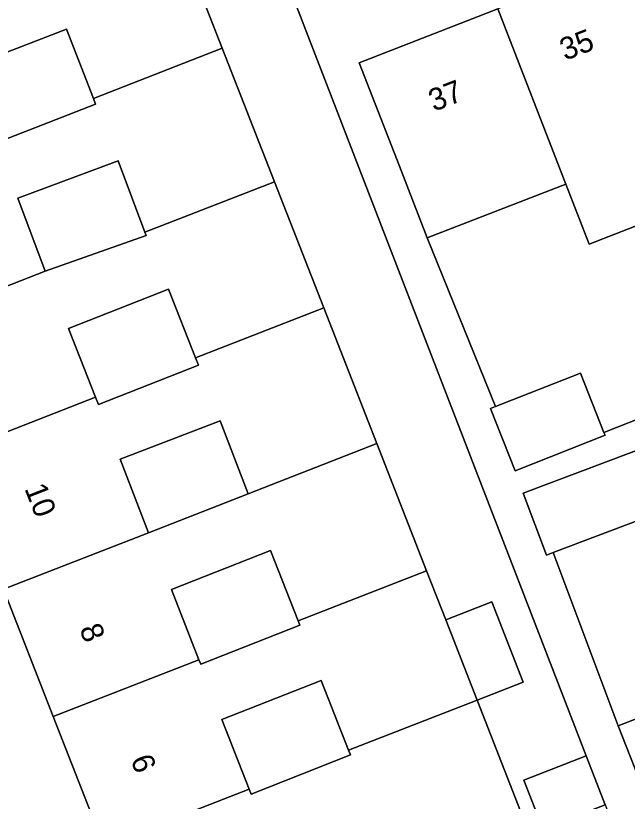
# Model space of a CAD drawing. Extents: x 159680 to 160786, y 387323 to 388340.
# Drawn here: x 160037.27 to 160064.76, y 387705.01 to 387740.35 of the extents above; entities that cross this region are included whole.
import ezdxf

# ---------------------------------------------------------------- set-up
doc = ezdxf.new("R2010")
doc.units = 0
for name, color, linetype in [('IMGEO_Erf', 7, 'Continuous'), ('IMGEO_Pand', 7, 'Continuous'), ('IMGEO_Pand_nummerreeks', 7, 'Continuous')]:
    doc.layers.add(name, color=color, linetype=linetype)

msp = doc.modelspace()

# ---------------------------------------------------------------- linework, layer by layer
at = {"layer": 'IMGEO_Erf'}
for points in [[(160063.763, 387704.855), (160060.968, 387703.763), (160060.112, 387705.953), (160062.906, 387707.046), (160049.712, 387741.251), (160047.668, 387746.549), (160047.477, 387746.967)], [(160044.3, 387744.642), (160046.55, 387738.886), (160048.898, 387732.879), (160051.117, 387727.204), (160053.501, 387721.103), (160055.739, 387715.38), (160056.604, 387713.166), (160058.678, 387713.977), (160060.087, 387710.373), (160058.013, 387709.563), (160060.342, 387703.605), (160062.693, 387697.59), (160056.921, 387695.334), (160055.624, 387698.652), (160051.143, 387696.9), (160052.452, 387693.552), (160045.92, 387690.998), (160043.556, 387697.046), (160041.227, 387703.003), (160038.953, 387708.82), (160036.716, 387714.544)], [(160049.712, 387741.251), (160062.906, 387707.046), (160063.763, 387704.855), (160067.164, 387696.141)], [(160068.113, 387723.336), (160063.713, 387721.604), (160063.764, 387721.474), (160059.714, 387719.879), (160058.612, 387722.678), (160058.842, 387722.769), (160055.766, 387730.35), (160054.513, 387733.571), (160052.7, 387738.23), (160058.934, 387740.655)], [(160068.893, 387732.348), (160063.049, 387730.075), (160061.999, 387732.775), (160055.766, 387730.35), (160058.842, 387722.769), (160062.662, 387724.273), (160063.713, 387721.604), (160068.113, 387723.336)], [(160065.622, 387705.162), (160064.358, 387708.4), (160061.428, 387716.201), (160061.123, 387716.086), (160060.074, 387718.864), (160066.203, 387721.178)], [(160067.252, 387718.4), (160061.428, 387716.201), (160064.358, 387708.4), (160070.388, 387710.753)]]:
    msp.add_lwpolyline(points, dxfattribs=at)
for points in [[(160040.757, 387736.624), (160039.547, 387739.743), (160035.038, 387737.994), (160036.254, 387734.86), (160036.348, 387734.617), (160040.857, 387736.366)], [(160038.589, 387728.848), (160043.128, 387730.452), (160043.071, 387730.603), (160041.869, 387733.821), (160037.36, 387732.135)], [(160040.985, 387722.858), (160045.482, 387724.623), (160045.352, 387724.953), (160044.139, 387728.043), (160039.642, 387726.278), (160040.854, 387723.191)], [(160046.457, 387722.115), (160041.962, 387720.394), (160043.229, 387717.087), (160047.71, 387718.842)], [(160045.581, 387711.183), (160050.035, 387712.929), (160049.959, 387713.123), (160048.719, 387716.285), (160044.265, 387714.539), (160045.504, 387711.378)], [(160052.233, 387707.306), (160050.995, 387710.446), (160046.533, 387708.686), (160047.768, 387705.557), (160047.855, 387705.336), (160052.316, 387707.096)]]:
    msp.add_lwpolyline(points, close=True, dxfattribs=at)
at = {"layer": 'IMGEO_Pand'}
for points in [[(160046.55, 387738.886), (160044.3, 387744.642), (160027.515, 387738.08), (160029.764, 387732.326), (160036.254, 387734.86), (160035.038, 387737.994), (160039.547, 387739.743), (160040.757, 387736.624)], [(160064.777, 387742.928), (160058.934, 387740.655), (160061.999, 387732.775), (160063.049, 387730.075), (160068.893, 387732.348), (160067.843, 387735.048)], [(160058.934, 387740.655), (160052.7, 387738.23), (160054.513, 387733.571), (160055.766, 387730.35), (160061.999, 387732.775)], [(160040.757, 387736.624), (160040.857, 387736.366), (160036.348, 387734.617), (160036.254, 387734.86), (160029.764, 387732.326), (160032.112, 387726.319), (160038.589, 387728.848), (160037.36, 387732.135), (160041.869, 387733.821), (160043.071, 387730.603), (160048.898, 387732.879), (160046.55, 387738.886)], [(160032.112, 387726.319), (160034.331, 387720.644), (160040.854, 387723.191), (160039.642, 387726.278), (160044.139, 387728.043), (160045.352, 387724.953), (160051.117, 387727.204), (160048.898, 387732.879), (160043.071, 387730.603), (160043.128, 387730.452), (160038.589, 387728.848)], [(160043.229, 387717.087), (160041.962, 387720.394), (160046.457, 387722.115), (160047.71, 387718.842), (160053.501, 387721.103), (160051.117, 387727.204), (160045.352, 387724.953), (160045.482, 387724.623), (160040.985, 387722.858), (160040.854, 387723.191), (160034.331, 387720.644), (160036.716, 387714.544)], [(160062.662, 387724.273), (160058.842, 387722.769), (160058.612, 387722.678), (160059.714, 387719.879), (160063.764, 387721.474), (160063.713, 387721.604)], [(160036.716, 387714.544), (160038.953, 387708.82), (160045.504, 387711.378), (160044.265, 387714.539), (160048.719, 387716.285), (160049.959, 387713.123), (160055.739, 387715.38), (160053.501, 387721.103), (160047.71, 387718.842), (160043.229, 387717.087)], [(160066.327, 387720.851), (160066.203, 387721.178), (160060.074, 387718.864), (160061.123, 387716.086), (160061.428, 387716.201), (160067.252, 387718.4)], [(160050.995, 387710.446), (160052.233, 387707.306), (160058.013, 387709.563), (160056.604, 387713.166), (160055.739, 387715.38), (160049.959, 387713.123), (160050.035, 387712.929), (160045.581, 387711.183), (160045.504, 387711.378), (160038.953, 387708.82), (160041.227, 387703.003), (160047.768, 387705.557), (160046.533, 387708.686)], [(160056.604, 387713.166), (160058.013, 387709.563), (160060.087, 387710.373), (160058.678, 387713.977)], [(160070.388, 387710.753), (160064.358, 387708.4), (160065.622, 387705.162), (160067.439, 387700.504), (160073.469, 387702.857)], [(160052.233, 387707.306), (160052.316, 387707.096), (160047.855, 387705.336), (160047.768, 387705.557), (160041.227, 387703.003), (160043.556, 387697.046), (160050.105, 387699.603), (160048.873, 387702.847), (160053.305, 387704.53), (160054.519, 387701.332), (160060.342, 387703.605), (160058.013, 387709.563)], [(160060.968, 387703.763), (160063.763, 387704.855), (160062.906, 387707.046), (160060.112, 387705.953)]]:
    msp.add_lwpolyline(points, close=True, dxfattribs=at)

# ---------------------------------------------------------------- texts
at = {"layer": 'IMGEO_Pand_nummerreeks'}
for s, rotation, p in [('35', 21.2567, (160061.967, 387738.315)), ('37', 21.2567, (160056.069, 387736.021)), ('10', 291.3512, (160037.648, 387719.081)), ('8', 291.3512, (160040.116, 387712.767)), ('6', 291.3539, (160042.415, 387706.885))]:
    msp.add_text(s, height=1, rotation=rotation, dxfattribs=at).set_placement(p)

doc.saveas('drawing.dxf')
